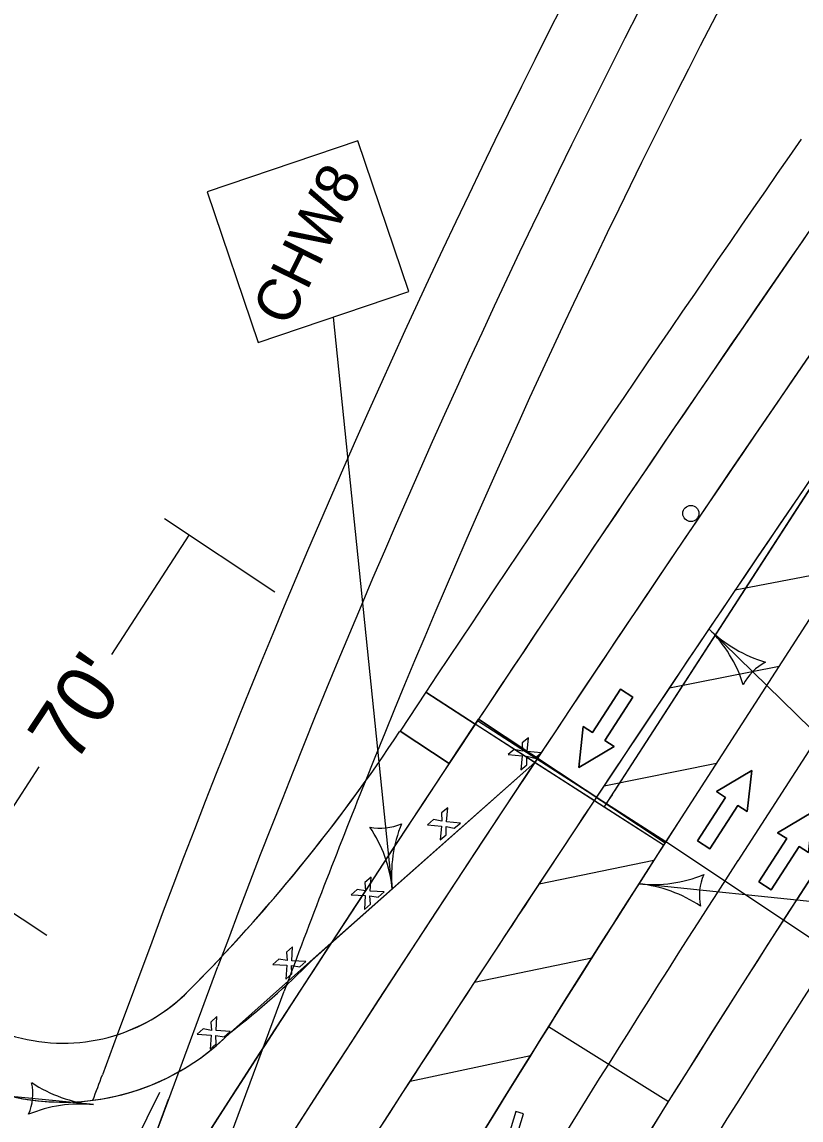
# Model space of a CAD drawing. Extents: x 14097936 to 14128734, y 8632000 to 8683104.
# Drawn here: x 14119063.6 to 14119195.8, y 8668855.4 to 8669041.8 of the extents above; entities that cross this region are included whole.
import ezdxf

# ---------------------------------------------------------------- set-up
doc = ezdxf.new("R2010")
doc.units = 0
for name, color, linetype in [('Cell', 7, 'Continuous'), ('dsn_stg_shd_prev', 7, 'Continuous'), ('dsnPaintExistingChannelizingLaneWhite', 7, 'Continuous'), ('dsnPaintExistingDoubleCenterYellow', 7, 'Continuous'), ('dsnPaintExistingEdgeLineRightWhite', 7, 'Continuous'), ('dsnPaintPlaceBrokenLaneWhite', 7, 'Continuous'), ('dsnPaintPlaceChannelizingLaneWhite', 7, 'Continuous'), ('dsnPaintPlaceChannelizingLaneYellow', 7, 'Continuous'), ('dsnPaintPlaceEdgeLineRightWhite', 7, 'Continuous'), ('dsnPaintPlaceStopLineWhite', 7, 'Continuous'), ('dsnPavementRmvl', 7, 'Continuous'), ('dsnShadingPaved', 7, 'Continuous'), ('dsnStdLabel', 7, 'Continuous'), ('dsnStgShadingPrevPav', 7, 'Continuous'), ('dsnStgShadingPropPav', 7, 'Continuous'), ('dsnTapePlaceChannelizingLaneWhite', 7, 'Continuous'), ('dsnTapeRemoveChannelizingLaneWhite', 7, 'Continuous'), ('dsnTapeRemoveChannelizingLaneYellow', 7, 'Continuous'), ('dsnTapeRemoveDoubleCenterYellow', 7, 'Continuous'), ('Level 2', 7, 'Continuous'), ('Level 5', 7, 'Continuous'), ('Text', 7, 'Continuous'), ('trf_Cells1', 7, 'Continuous')]:
    doc.layers.add(name, color=color, linetype=linetype)

msp = doc.modelspace()

# ---------------------------------------------------------------- linework, layer by layer
at = {"layer": 'Cell'}
for p, q in [((14119149.56, 8668920.32), (14119148.5, 8668919.45)), ((14119149.34, 8668917.95), (14119149.56, 8668920.32)), ((14119147.16, 8668918.33), (14119146.1, 8668917.45)), ((14119148.55, 8668918.02), (14119147.16, 8668918.33)), ((14119148.5, 8668919.45), (14119148.55, 8668918.02)), ((14119146.1, 8668917.45), (14119148.48, 8668917.23)), ((14119148.48, 8668917.23), (14119148.26, 8668914.85)), ((14119149.31, 8668915.73), (14119149.27, 8668917.16)), ((14119149.27, 8668917.16), (14119150.66, 8668916.85)), ((14119151.72, 8668917.73), (14119149.34, 8668917.95)), ((14119150.66, 8668916.85), (14119151.72, 8668917.73)), ((14119148.26, 8668914.85), (14119149.31, 8668915.73)), ((14119135.87, 8668908.42), (14119134.81, 8668907.54)), ((14119134.81, 8668907.54), (14119134.85, 8668906.12)), ((14119135.64, 8668906.04), (14119135.87, 8668908.42)), ((14119133.46, 8668906.42), (14119132.4, 8668905.54)), ((14119132.4, 8668905.54), (14119134.78, 8668905.32)), ((14119134.85, 8668906.12), (14119133.46, 8668906.42)), ((14119134.78, 8668905.32), (14119134.56, 8668902.95)), ((14119135.62, 8668903.83), (14119135.57, 8668905.25)), ((14119135.57, 8668905.25), (14119136.96, 8668904.94)), ((14119138.02, 8668905.82), (14119135.64, 8668906.04)), ((14119136.96, 8668904.94), (14119138.02, 8668905.82)), ((14119134.56, 8668902.95), (14119135.62, 8668903.83)), ((14119122.84, 8668896.65), (14119121.81, 8668895.74)), ((14119122.7, 8668894.27), (14119122.84, 8668896.65)), ((14119120.5, 8668894.57), (14119119.48, 8668893.66)), ((14119121.91, 8668894.31), (14119120.5, 8668894.57)), ((14119121.81, 8668895.74), (14119121.91, 8668894.31)), ((14119125.08, 8668894.13), (14119122.7, 8668894.27)), ((14119124.06, 8668893.22), (14119125.08, 8668894.13)), ((14119119.48, 8668893.66), (14119121.86, 8668893.52)), ((14119121.86, 8668893.52), (14119121.72, 8668891.14)), ((14119122.75, 8668892.05), (14119122.65, 8668893.47)), ((14119122.65, 8668893.47), (14119124.06, 8668893.22)), ((14119121.72, 8668891.14), (14119122.75, 8668892.05)), ((14119109.51, 8668884.82), (14119108.48, 8668883.91)), ((14119109.37, 8668882.44), (14119109.51, 8668884.82)), ((14119108.48, 8668883.91), (14119108.58, 8668882.48)), ((14119107.18, 8668882.74), (14119106.15, 8668881.83)), ((14119106.15, 8668881.83), (14119108.53, 8668881.69)), ((14119108.58, 8668882.48), (14119107.18, 8668882.74)), ((14119108.53, 8668881.69), (14119108.39, 8668879.31)), ((14119109.42, 8668880.22), (14119109.33, 8668881.64)), ((14119109.33, 8668881.64), (14119110.73, 8668881.39)), ((14119111.75, 8668882.3), (14119109.37, 8668882.44)), ((14119110.73, 8668881.39), (14119111.75, 8668882.3)), ((14119108.39, 8668879.31), (14119109.42, 8668880.22)), ((14119096.67, 8668872.96), (14119095.65, 8668872.04)), ((14119095.65, 8668872.04), (14119095.74, 8668870.62)), ((14119096.54, 8668870.58), (14119096.67, 8668872.96)), ((14119094.34, 8668870.88), (14119093.31, 8668869.97)), ((14119093.31, 8668869.97), (14119095.7, 8668869.83)), ((14119095.74, 8668870.62), (14119094.34, 8668870.88)), ((14119095.7, 8668869.83), (14119095.56, 8668867.45)), ((14119096.58, 8668868.36), (14119096.49, 8668869.78)), ((14119096.49, 8668869.78), (14119097.89, 8668869.52)), ((14119098.92, 8668870.44), (14119096.54, 8668870.58)), ((14119097.89, 8668869.52), (14119098.92, 8668870.44)), ((14119095.56, 8668867.45), (14119096.58, 8668868.36))]:
    msp.add_line(p, q, dxfattribs=at)
msp.add_circle((14119177.14, 8668958.39), 1.37, dxfattribs=at)
at = {"layer": 'dsn_stg_shd_prev'}
for p, q in [((14119162.43, 8668908.54), (14119212.98, 8668986.84)), ((14119212.98, 8668986.84), (14119164.55, 8668911.89)), ((14119150.62, 8668916.12), (14119140.53, 8668922.62)), ((14119136.09, 8668915.93), (14119127.76, 8668921.44)), ((14119160.72, 8668909.63), (14119150.62, 8668916.12)), ((14119162.4, 8668908.55), (14119160.72, 8668909.63)), ((14119172.49, 8668902.05), (14119162.43, 8668908.54))]:
    msp.add_line(p, q, dxfattribs=at)
for points in [[(14119140.53, 8668922.62), (14119132.12, 8668928.03), (14119127.76, 8668921.44), (14119136.1, 8668915.93)], [(14119172.49, 8668902.05), (14119162.43, 8668908.54), (14119140.53, 8668922.62), (14119141.1, 8668923.47), (14119172.76, 8668902.45)]]:
    msp.add_lwpolyline(points, close=True, dxfattribs=at)
for centre, radius, start, end in [((14123732.59, 8665873.82), 5512, 146.41866, 157.1633), ((14118885.9, 8669081.47), 290, 315.2544, 326.5091), ((14123732.59, 8665873.82), 5512, 146.50213, 150.36196), ((14120766.72, 8667876.88), 1907.4, 147.13706, 147.25659), ((14121591.75, 8667345.11), 2876.96, 147.23629, 155.33788), ((14121592.11, 8667345.68), 2876.95, 147.23628, 151.16499), ((14119070.57, 8668898.44), 30, 193.5302, 315.2544), ((14121592.11, 8667345.68), 2842.95, 147.24613, 151.16499)]:
    msp.add_arc(centre, radius, start, end, dxfattribs=at)
at = {"layer": 'dsnPaintExistingChannelizingLaneWhite'}
msp.add_line((14119085.61, 8668885.62), (14119079.76, 8668869.88), dxfattribs=at)
for radius, end in [(1512, 159.62671), (1488, 158.15787)]:
    msp.add_arc((14120503.02, 8668359.24), radius, 147.24256, end, dxfattribs=at)
at = {"layer": 'dsnPaintExistingDoubleCenterYellow'}
msp.add_arc((14120503.02, 8668359.24), 1500, 147.24256, 159.62671, dxfattribs=at)
at = {"layer": 'dsnPaintExistingEdgeLineRightWhite'}
msp.add_arc((14119070.57, 8668898.44), 40, 193.5302, 277.2674, dxfattribs=at)
at = {"layer": 'dsnPaintPlaceBrokenLaneWhite'}
msp.add_line((14119527.44, 8669429.79), (14119185.09, 8668899.43), dxfattribs=at)
for centre, radius, start, end in [((14121592.11, 8667345.68), 2864.95, 147.15737, 151.16499), ((14123732.96, 8665874.38), 5500, 147.11705, 157.1633)]:
    msp.add_arc(centre, radius, start, end, dxfattribs=at)
at = {"layer": 'dsnPaintPlaceChannelizingLaneWhite'}
msp.add_arc((14123732.96, 8665874.38), 5500, 145.2497, 146.42378, dxfattribs=at)
at = {"layer": 'dsnPaintPlaceChannelizingLaneYellow'}
for p, q in [((14119175.01, 8668905.94), (14119397.41, 8669250.48)), ((14119184.67, 8668945.4), (14119202.74, 8668948.91)), ((14119173.5, 8668928.81), (14119192.15, 8668932.49)), ((14119162.4, 8668912.17), (14119181.51, 8668916.02)), ((14119151.36, 8668895.49), (14119170.86, 8668899.5)), ((14119140.38, 8668878.78), (14119160.32, 8668882.94)), ((14119129.46, 8668862.02), (14119149.92, 8668866.37))]:
    msp.add_line(p, q, dxfattribs=at)
for centre, radius, start, end in [((14123732.96, 8665874.38), 5488, 145.2497, 146.41498), ((14123732.96, 8665874.38), 5488, 146.41498, 147.75486), ((14121592.11, 8667345.68), 2876.95, 147.15737, 149.16283)]:
    msp.add_arc(centre, radius, start, end, dxfattribs=at)
at = {"layer": 'dsnPaintPlaceEdgeLineRightWhite'}
for p, q in [((14119195.17, 8668892.92), (14119537.53, 8669423.29)), ((14119116.09, 8668885.47), (14119098.98, 8668870.28))]:
    msp.add_line(p, q, dxfattribs=at)
for centre, radius, start, end in [((14121592.11, 8667345.68), 2852.95, 147.15737, 151.16499), ((14119070.57, 8668898.44), 40, 277.2674, 315.2544)]:
    msp.add_arc(centre, radius, start, end, dxfattribs=at)
at = {"layer": 'dsnPaintPlaceStopLineWhite'}
msp.add_line((14119152.99, 8668871.3), (14119173.34, 8668858.57), dxfattribs=at)
at = {"layer": 'dsnPavementRmvl'}
msp.add_line((14119085.61, 8668885.62), (14119079.76, 8668869.88), dxfattribs=at)
for centre, radius, start, end in [((14120503.02, 8668359.24), 1512, 147.24256, 159.62671), ((14120503.02, 8668359.24), 1488, 147.24256, 158.15787), ((14118885.9, 8669081.47), 290, 315.2544, 324.4478), ((14119070.57, 8668898.44), 30, 287.8557, 315.2544)]:
    msp.add_arc(centre, radius, start, end, dxfattribs=at)
at = {"layer": 'dsnShadingPaved'}
for p, q in [((14119175.01, 8668905.94), (14119517.35, 8669436.29)), ((14119150.63, 8668916.13), (14119115.98, 8668885.3)), ((14119112.81, 8668882.49), (14119115.98, 8668885.3))]:
    msp.add_line(p, q, dxfattribs=at)
msp.add_lwpolyline([(14119537.53, 8669423.29), (14119537.53, 8669423.29), (14119195.17, 8668892.92)], dxfattribs=at)
for centre, radius, start, end in [((14123732.96, 8665874.38), 5500, 145.2497, 157.1633), ((14123732.96, 8665874.38), 5488, 145.2497, 157.1633), ((14119233.62, 8668936.54), 213, 167.9329, 217.7768), ((14123732.96, 8665874.38), 5500, 146.42378, 157.1633), ((14121592.11, 8667345.68), 2876.95, 147.15737, 157.1633), ((14121592.11, 8667345.68), 2852.95, 147.15737, 157.1633), ((14119070.57, 8668898.44), 40, 193.5302, 315.2544), ((14123655.03, 8665915.77), 5424.12, 146.80648, 157.24675), ((14123056.19, 8666307.54), 4708.51, 146.80648, 147.95139), ((14119004.73, 8668991.06), 153.2, 307.9637, 314.8691)]:
    msp.add_arc(centre, radius, start, end, dxfattribs=at)
at = {"layer": 'dsnStdLabel'}
for p, q in [((14119126.44, 8668894.68), (14119116.46, 8668991.74)), ((14119106.51, 8668945.03), (14119087.76, 8668957.48)), ((14119091.93, 8668954.71), (14119078.8, 8668934.44)), ((14119231.14, 8668888.99), (14119180.2, 8668938.78)), ((14119066.47, 8668915.39), (14119053.88, 8668895.95)), ((14119067.8, 8668886.71), (14119049.05, 8668899.15)), ((14119231.14, 8668888.99), (14119168.3, 8668895.51)), ((14119075.72, 8668858.02), (14118971.79, 8668868.09))]:
    msp.add_line(p, q, dxfattribs=at)
msp.add_lwpolyline([(14119103.67, 8668987.41), (14119129.24, 8668996.06), (14119120.59, 8669021.64), (14119095.02, 8669012.98)], close=True, dxfattribs=at)
for centre, radius, start, end in [((14119164.16, 8668922.37), 22.95, 17.5771, 45.6484), ((14119196.25, 8668955.19), 22.95, 225.6482, 253.7195), ((14119193.96, 8668925.33), 8.86, 117.914, 153.3825), ((14119124.47, 8668913.82), 8.86, 258.1397, 293.6082), ((14119149.27, 8668897.03), 22.95, 157.8027, 185.874), ((14119103.61, 8668892.33), 22.95, 5.8739, 33.9452), ((14119170.67, 8668918.34), 22.95, 264.0752, 292.1465), ((14119187.44, 8668893.52), 8.86, 156.341, 191.8095), ((14119165.94, 8668872.68), 22.95, 56.004, 84.0753), ((14119056.57, 8668859.87), 8.86, 336.7303, 12.1988), ((14119077.94, 8668880.86), 22.95, 236.3934, 264.4647), ((14119073.51, 8668835.17), 22.95, 84.4645, 112.5358)]:
    msp.add_arc(centre, radius, start, end, dxfattribs=at)
at = {"layer": 'dsnStgShadingPrevPav'}
for p, q in [((14119150.99, 8668916.68), (14119140.9, 8668923.18)), ((14119161.09, 8668910.19), (14119150.99, 8668916.68)), ((14119162.8, 8668909.1), (14119161.09, 8668910.19)), ((14119161.09, 8668910.19), (14119161.93, 8668909.65)), ((14119162.77, 8668909.1), (14119161.09, 8668910.19)), ((14119172.86, 8668902.61), (14119162.8, 8668909.1))]:
    msp.add_line(p, q, dxfattribs=at)
for centre, radius, start, end in [((14123732.96, 8665874.38), 5512, 146.41866, 157.1633), ((14119422.1, 8669313), 479.98, 237.1765, 237.296), ((14121592.12, 8667345.67), 2876.96, 147.23629, 155.33788)]:
    msp.add_arc(centre, radius, start, end, dxfattribs=at)
at = {"layer": 'dsnStgShadingPropPav'}
for p, q in [((14119132.12, 8668928.03), (14119140.53, 8668922.62)), ((14119136.09, 8668915.93), (14119127.76, 8668921.44)), ((14119085.61, 8668885.62), (14119079.76, 8668869.88))]:
    msp.add_line(p, q, dxfattribs=at)
msp.add_lwpolyline([(14119420.33, 8669223.29), (14119201.18, 8668883.8), (14119172.86, 8668902.61), (14119172.76, 8668902.45), (14119141.1, 8668923.47)], dxfattribs=at)
for points in [[(14119140.53, 8668922.62), (14119132.12, 8668928.03), (14119127.76, 8668921.44), (14119136.1, 8668915.93)], [(14119140.53, 8668922.62), (14119141.1, 8668923.47), (14119172.76, 8668902.45), (14119172.49, 8668902.05)]]:
    msp.add_lwpolyline(points, close=True, dxfattribs=at)
for centre, radius, start, end in [((14120503.02, 8668359.24), 1512, 147.24256, 159.62671), ((14120503.02, 8668359.24), 1488, 147.24256, 158.15787), ((14123732.96, 8665874.38), 5522, 145.2497, 146.42709), ((14123732.96, 8665874.38), 5512, 145.2497, 146.42562), ((14123732.96, 8665874.38), 5512, 145.2497, 146.41498), ((14118885.9, 8669081.47), 290, 315.2544, 326.5091), ((14123732.59, 8665873.82), 5512, 146.50213, 150.36196), ((14118885.9, 8669081.47), 290, 315.2544, 324.4478), ((14121592.11, 8667345.68), 2876.95, 147.23628, 151.16499), ((14119070.57, 8668898.44), 30, 193.5302, 315.2544), ((14121592.11, 8667345.68), 2842.95, 147.24613, 151.16499), ((14119070.57, 8668898.44), 30, 287.8557, 315.2544)]:
    msp.add_arc(centre, radius, start, end, dxfattribs=at)
at = {"layer": 'dsnTapePlaceChannelizingLaneWhite'}
msp.add_line((14119116.09, 8668885.47), (14119150.63, 8668916.13), dxfattribs=at)
at = {"layer": 'dsnTapeRemoveChannelizingLaneWhite'}
for p, q in [((14118983.04, 8668540.5), (14119108.11, 8668877.26)), ((14119079.76, 8668869.88), (14119077.24, 8668863.09)), ((14119079.76, 8668869.88), (14119077.24, 8668863.09))]:
    msp.add_line(p, q, dxfattribs=at)
for centre, start, end in [((14120503.02, 8668359.24), 158.15787, 159.62671), ((14120503.02, 8668359.24), 158.15787, 159.62671), ((14117682.33, 8669381.12), 339.44858, 339.62671), ((14117682.33, 8669381.12), 339.44858, 339.62671)]:
    msp.add_arc(centre, 1488, start, end, dxfattribs=at)
at = {"layer": 'dsnTapeRemoveChannelizingLaneYellow'}
msp.add_line((14118971.78, 8668544.68), (14119088.49, 8668858.92), dxfattribs=at)
msp.add_arc((14117682.32, 8669381.12), 1500, 329.20119, 339.62671, dxfattribs=at)
at = {"layer": 'dsnTapeRemoveDoubleCenterYellow'}
msp.add_line((14119088.49, 8668858.92), (14119096.86, 8668881.44), dxfattribs=at)
msp.add_line((14119088.49, 8668858.92), (14119096.86, 8668881.44), dxfattribs=at)
at = {"layer": 'Level 2'}
for points in [[(14119167.28, 8668927.18), (14119165.18, 8668928.54), (14119160.44, 8668921.18), (14119158.86, 8668922.2), (14119158.1, 8668915.26), (14119164.12, 8668918.81), (14119162.54, 8668919.83)], [(14119178.28, 8668902.82), (14119180.37, 8668901.46), (14119185.13, 8668908.81), (14119186.71, 8668907.79), (14119187.48, 8668914.73), (14119181.46, 8668911.19), (14119183.04, 8668910.17)], [(14119188.65, 8668895.83), (14119190.75, 8668894.47), (14119195.51, 8668901.82), (14119197.08, 8668900.8), (14119197.86, 8668907.74), (14119191.83, 8668904.19), (14119193.41, 8668903.18)]]:
    msp.add_lwpolyline(points, close=True, dxfattribs=at)
at = {"layer": 'Level 5'}
for points in [[(14119162.54, 8668919.83), (14119164.12, 8668918.81), (14119158.1, 8668915.26), (14119158.86, 8668922.2), (14119160.44, 8668921.18), (14119165.18, 8668928.54), (14119167.28, 8668927.18), (14119162.54, 8668919.83)], [(14119183.04, 8668910.17), (14119181.46, 8668911.19), (14119187.48, 8668914.73), (14119186.71, 8668907.79), (14119185.13, 8668908.81), (14119180.37, 8668901.46), (14119178.28, 8668902.82), (14119183.04, 8668910.17)], [(14119193.41, 8668903.18), (14119191.83, 8668904.19), (14119197.86, 8668907.74), (14119197.08, 8668900.8), (14119195.51, 8668901.82), (14119190.75, 8668894.47), (14119188.65, 8668895.83), (14119193.41, 8668903.18)]]:
    msp.add_lwpolyline(points, dxfattribs=at)
at = {"layer": 'Text'}
msp.add_lwpolyline([(14119086.91, 8668860.05), (14119058.81, 8668803.21), (14119091.35, 8668802.46)], dxfattribs=at)
at = {"layer": 'trf_Cells1'}
msp.add_lwpolyline([(14119142.61, 8668836.38), (14119148.73, 8668856.46), (14119147.45, 8668856.85), (14119141.34, 8668836.77)], close=True, dxfattribs=at)

# ---------------------------------------------------------------- texts
at = {"layer": 'dsnStdLabel'}
for s, height, rotation, p in [('CHW8', 7.2, 63.6912, (14119108.89, 8668989.85)), ("70'", 10, 56.6002, (14119072.45, 8668915.56))]:
    msp.add_text(s, height=height, rotation=rotation, dxfattribs=at).set_placement(p)

doc.saveas('drawing.dxf')
